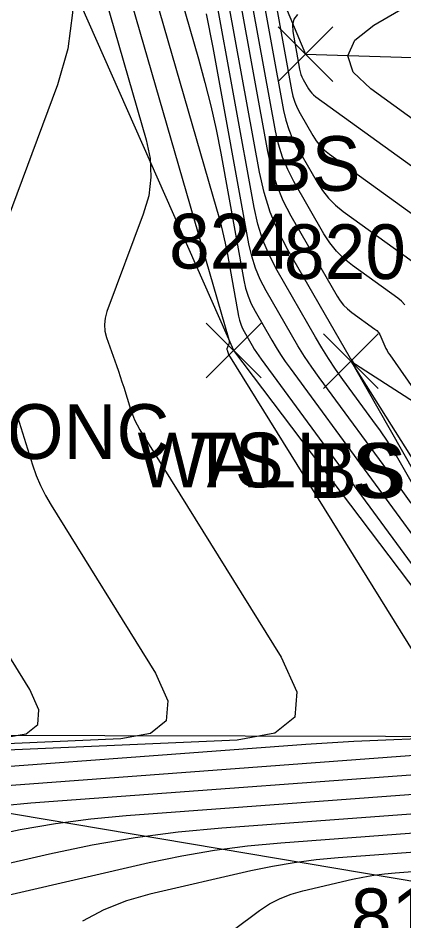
# Model space of a CAD drawing. Extents: x 1650836 to 1652450, y 332578 to 333908.
# Drawn here: x 1652038.33 to 1652052.42, y 332730.94 to 332763.95 of the extents above; entities that cross this region are included whole.
import ezdxf

# ---------------------------------------------------------------- set-up
doc = ezdxf.new("R2010")
doc.units = 0
for name, color, linetype in [('L_A', 7, 'Continuous'), ('L_I', 7, 'Continuous'), ('L_TIC', 7, 'Continuous'), ('LAWE', 7, 'Continuous'), ('LELB', 7, 'Continuous'), ('LSOGCMA', 7, 'Continuous'), ('LSOGCMI', 7, 'Continuous'), ('LW', 7, 'Continuous'), ('M_C', 7, 'Continuous')]:
    doc.layers.add(name, color=color, linetype=linetype)

msp = doc.modelspace()

# ---------------------------------------------------------------- linework, layer by layer
at = {"layer": 'L_TIC'}
for points in [[(1652047.825, 332761.633), (1652049.825, 332763.633)], [(1652049.825, 332761.633), (1652047.825, 332763.633)], [(1652045.201, 332750.794), (1652047.201, 332752.794)], [(1652047.201, 332750.794), (1652045.201, 332752.794)], [(1652045.201, 332750.794), (1652047.201, 332752.794)], [(1652047.201, 332750.794), (1652045.201, 332752.794)], [(1652049.483, 332750.409), (1652051.483, 332752.409)], [(1652051.483, 332750.409), (1652049.483, 332752.409)], [(1652049.483, 332750.409), (1652051.483, 332752.409)], [(1652051.483, 332750.409), (1652049.483, 332752.409)]]:
    msp.add_lwpolyline(points, dxfattribs=at)
at = {"layer": 'LAWE'}
msp.add_lwpolyline([(1651991.353, 332729.831), (1652016.528, 332734.243), (1652026.591, 332736.811), (1652054.126, 332732.169), (1652059.389, 332736.419), (1652073.187, 332741.436)], dxfattribs=at)
at = {"layer": 'LELB'}
for points in [[(1652023.947, 332796.746), (1652033.145, 332795.123), (1652040.892, 332784.647), (1652044.285, 332773.47), (1652048.825, 332762.633), (1652060.903, 332762.254), (1652066.549, 332756.035)], [(1652046.201, 332751.794), (1652032.797, 332782.109), (1652031.244, 332792.189)], [(1652050.483, 332751.409), (1652057.722, 332739.902)], [(1652050.483, 332751.409), (1652063.333, 332743.12), (1652057.722, 332739.902)], [(1652026.105, 332737.765), (1652056.867, 332737.688)]]:
    msp.add_lwpolyline(points, dxfattribs=at)
at = {"layer": 'LSOGCMA'}
for points in [[(1652036.584, 332778.551), (1652039.972, 332766.816), (1652040.25, 332765.477), (1652040.308, 332764.146), (1652040.148, 332762.823), (1652039.767, 332761.509), (1652037.169, 332754.567)], [(1652047.094, 332765.667), (1652048.02, 332760.574), (1652048.101, 332760.219), (1652048.21, 332759.874), (1652048.349, 332759.54), (1652048.516, 332759.217), (1652049.246, 332757.946), (1652049.443, 332757.641), (1652049.668, 332757.362), (1652049.923, 332757.108), (1652050.205, 332756.881), (1652053.031, 332754.839)], [(1652038.247, 332749.564), (1652038.37, 332749.175), (1652038.856, 332747.616), (1652038.99, 332747.232), (1652039.147, 332746.858), (1652039.327, 332746.495), (1652039.53, 332746.143), (1652043.345, 332739.998), (1652043.796, 332738.993), (1652043.736, 332738.259), (1652043.164, 332737.795), (1652042.079, 332737.602), (1652027.09, 332736.948)]]:
    msp.add_lwpolyline(points, dxfattribs=at)
at = {"layer": 'LSOGCMI'}
for points in [[(1652037.849, 332777.362), (1652043.006, 332759.5), (1652043.148, 332758.813), (1652043.178, 332758.13), (1652043.096, 332757.452), (1652042.901, 332756.778), (1652041.568, 332753.217), (1652041.501, 332752.981), (1652041.477, 332752.745), (1652041.496, 332752.509), (1652041.558, 332752.272), (1652041.92, 332751.245), (1652041.989, 332751.047), (1652042.056, 332750.849), (1652042.121, 332750.65), (1652042.184, 332750.451), (1652042.434, 332749.651), (1652042.502, 332749.454), (1652042.582, 332749.262), (1652042.675, 332749.076), (1652042.779, 332748.895), (1652047.933, 332740.592), (1652048.505, 332739.32), (1652048.429, 332738.391), (1652047.704, 332737.803), (1652046.331, 332737.558), (1652035.959, 332737.106)], [(1652054.072, 332738.689), (1652046.028, 332751.648), (1652046.023, 332751.657), (1652046.018, 332751.666), (1652046.014, 332751.676), (1652046.011, 332751.686), (1652045.998, 332751.726), (1652045.995, 332751.736), (1652045.991, 332751.746), (1652045.988, 332751.757), (1652045.985, 332751.767), (1652045.966, 332751.819), (1652045.963, 332751.831), (1652045.962, 332751.842), (1652045.963, 332751.854), (1652045.967, 332751.866), (1652046.034, 332752.047), (1652046.044, 332752.081), (1652046.048, 332752.115), (1652046.047, 332752.15), (1652046.04, 332752.184), (1652039.114, 332776.173)], [(1652040.379, 332774.984), (1652045.577, 332756.979), (1652045.691, 332756.563), (1652045.795, 332756.145), (1652045.888, 332755.724), (1652045.971, 332755.301), (1652046.38, 332753.048), (1652046.413, 332752.903), (1652046.457, 332752.763), (1652046.514, 332752.627), (1652046.582, 332752.496), (1652046.879, 332751.979), (1652046.955, 332751.85), (1652047.034, 332751.725), (1652047.117, 332751.601), (1652047.204, 332751.48), (1652055.816, 332739.744)], [(1652041.562, 332774.075), (1652044.917, 332762.455), (1652045.153, 332761.6), (1652045.366, 332760.74), (1652045.557, 332759.875), (1652045.727, 332759.005), (1652046.569, 332754.372), (1652046.636, 332754.074), (1652046.728, 332753.786), (1652046.844, 332753.507), (1652046.984, 332753.237), (1652047.595, 332752.173), (1652047.751, 332751.91), (1652047.914, 332751.651), (1652048.085, 332751.397), (1652048.263, 332751.147), (1652053.944, 332743.406)], [(1652057.194, 332739.635), (1652050.631, 332751.171), (1652050.623, 332751.186), (1652050.617, 332751.202), (1652050.612, 332751.218), (1652050.609, 332751.235), (1652050.597, 332751.312), (1652050.594, 332751.325), (1652050.59, 332751.337), (1652050.585, 332751.348), (1652050.578, 332751.359), (1652050.537, 332751.418), (1652050.534, 332751.424), (1652050.531, 332751.43), (1652050.525, 332751.443), (1652050.523, 332751.446), (1652050.521, 332751.449), (1652050.519, 332751.452), (1652050.516, 332751.454), (1652050.484, 332751.477), (1652050.478, 332751.482), (1652050.473, 332751.487), (1652050.468, 332751.493), (1652050.464, 332751.5), (1652048.179, 332755.479), (1652047.828, 332756.156), (1652047.538, 332756.855), (1652047.309, 332757.577), (1652047.141, 332758.321), (1652044.495, 332772.87)], [(1652045.389, 332770.319), (1652047.434, 332759.072), (1652047.573, 332758.457), (1652047.762, 332757.862), (1652048.001, 332757.284), (1652048.292, 332756.725), (1652049.982, 332753.781), (1652050.091, 332753.611), (1652050.217, 332753.456), (1652050.358, 332753.315), (1652050.515, 332753.189), (1652051.355, 332752.582), (1652051.425, 332752.524), (1652051.486, 332752.458), (1652051.537, 332752.383), (1652051.578, 332752.302), (1652051.722, 332751.958), (1652051.76, 332751.874), (1652051.803, 332751.791), (1652051.85, 332751.711), (1652051.901, 332751.634), (1652052.967, 332750.113)], [(1652057.123, 332739.208), (1652052.297, 332747.69), (1652052.062, 332748.089), (1652051.816, 332748.481), (1652051.559, 332748.865), (1652051.29, 332749.243), (1652050.194, 332750.737), (1652049.925, 332751.114), (1652049.667, 332751.499), (1652049.42, 332751.89), (1652049.184, 332752.288), (1652047.789, 332754.718), (1652047.504, 332755.267), (1652047.269, 332755.833), (1652047.083, 332756.417), (1652046.948, 332757.019), (1652044.791, 332768.878)], [(1652055.545, 332758.224), (1652051.209, 332761.357), (1652050.565, 332761.974), (1652050.369, 332762.569), (1652050.622, 332763.142), (1652051.324, 332763.692), (1652060.292, 332768.917)], [(1652052.45, 332753.466), (1652052.331, 332753.596), (1652052.193, 332753.711), (1652050.546, 332754.901), (1652050.237, 332755.149), (1652049.96, 332755.425), (1652049.715, 332755.729), (1652049.5, 332756.062), (1652048.404, 332757.971), (1652048.175, 332758.412), (1652047.986, 332758.868), (1652047.837, 332759.338), (1652047.727, 332759.823), (1652046.282, 332767.769)], [(1652047.725, 332764.561), (1652048.314, 332761.325), (1652048.365, 332761.099), (1652048.434, 332760.88), (1652048.522, 332760.668), (1652048.629, 332760.463), (1652049.092, 332759.655), (1652049.217, 332759.461), (1652049.361, 332759.284), (1652049.522, 332759.123), (1652049.702, 332758.979), (1652053.869, 332755.967)], [(1652052.679, 332746.216), (1652052.131, 332746.986), (1652049.322, 332750.815), (1652049.053, 332751.192), (1652048.794, 332751.577), (1652048.547, 332751.969), (1652048.311, 332752.368), (1652047.387, 332753.978), (1652047.174, 332754.387), (1652046.998, 332754.809), (1652046.86, 332755.246), (1652046.758, 332755.695), (1652045.454, 332762.873), (1652045.213, 332764.108)], [(1652048.533, 332764.084), (1652048.403, 332763.909), (1652048.344, 332763.699), (1652048.356, 332763.454), (1652048.607, 332762.076), (1652048.629, 332761.98), (1652048.658, 332761.887), (1652048.696, 332761.796), (1652048.741, 332761.709), (1652048.939, 332761.365), (1652048.992, 332761.282), (1652049.053, 332761.207), (1652049.122, 332761.138), (1652049.198, 332761.076), (1652054.707, 332757.096)], [(1652037.828, 332737.645), (1652038.623, 332737.787), (1652039.043, 332738.128), (1652039.088, 332738.666), (1652038.756, 332739.404), (1652036.281, 332743.391)], [(1652031.813, 332736.141), (1652048.842, 332737.403), (1652049.426, 332737.444), (1652050.011, 332737.481), (1652050.595, 332737.513), (1652051.18, 332737.541), (1652053.52, 332737.643)], [(1652056.543, 332737.268), (1652035.301, 332735.693)], [(1652055.967, 332736.519), (1652038.788, 332735.246), (1652037.78, 332735.152)], [(1652037.132, 332734.02), (1652038.407, 332734.288), (1652039.689, 332734.507), (1652040.979, 332734.677), (1652042.276, 332734.798), (1652055.39, 332735.77)], [(1652030.477, 332731.325), (1652039.476, 332733.399), (1652041.034, 332733.727), (1652042.601, 332733.995), (1652044.178, 332734.203), (1652045.763, 332734.351), (1652054.813, 332735.021)], [(1652035.675, 332731.362), (1652043.119, 332733.078), (1652044.309, 332733.328), (1652045.506, 332733.533), (1652046.71, 332733.691), (1652047.921, 332733.804), (1652054.237, 332734.273)], [(1652053.66, 332733.524), (1652050.012, 332733.253), (1652049.209, 332733.178), (1652048.41, 332733.073), (1652047.617, 332732.937), (1652046.828, 332732.771), (1652043.139, 332731.921), (1652042.282, 332731.677), (1652041.463, 332731.349), (1652040.683, 332730.937)], [(1652038.587, 332724.928), (1652047.149, 332731.319), (1652047.514, 332731.563), (1652047.897, 332731.766), (1652048.3, 332731.927), (1652048.722, 332732.047), (1652050.536, 332732.465), (1652050.924, 332732.547), (1652051.315, 332732.614), (1652051.707, 332732.665), (1652052.102, 332732.702), (1652053.687, 332732.82)]]:
    msp.add_lwpolyline(points, dxfattribs=at)
at = {"layer": 'LW'}
msp.add_lwpolyline([(1652056.867, 332737.688), (1652046.201, 332751.794)], dxfattribs=at)

# ---------------------------------------------------------------- texts
at = {"layer": 'L_A'}
for s, p in [('BS', (1652047.265, 332757.633)), ('WALL', (1652042.69, 332746.794)), ('TS', (1652044.611, 332746.794)), ('TS', (1652048.893, 332746.409)), ('BS', (1652048.924, 332746.409))]:
    msp.add_text(s, height=2, dxfattribs=at).set_placement(p)
at = {"layer": 'L_I'}
for s, p in [('824', (1652043.839, 332754.794)), ('824', (1652043.839, 332754.794)), ('820', (1652048.034, 332754.409)), ('820', (1652048.034, 332754.409)), ('814', (1652050.479, 332730.131))]:
    msp.add_text(s, height=2, dxfattribs=at).set_placement(p)
at = {"layer": 'M_C'}
msp.add_text('2 IN FILLED W/ CONC', height=2, dxfattribs=at).set_placement((1652016.508, 332747.834))

doc.saveas('drawing.dxf')
